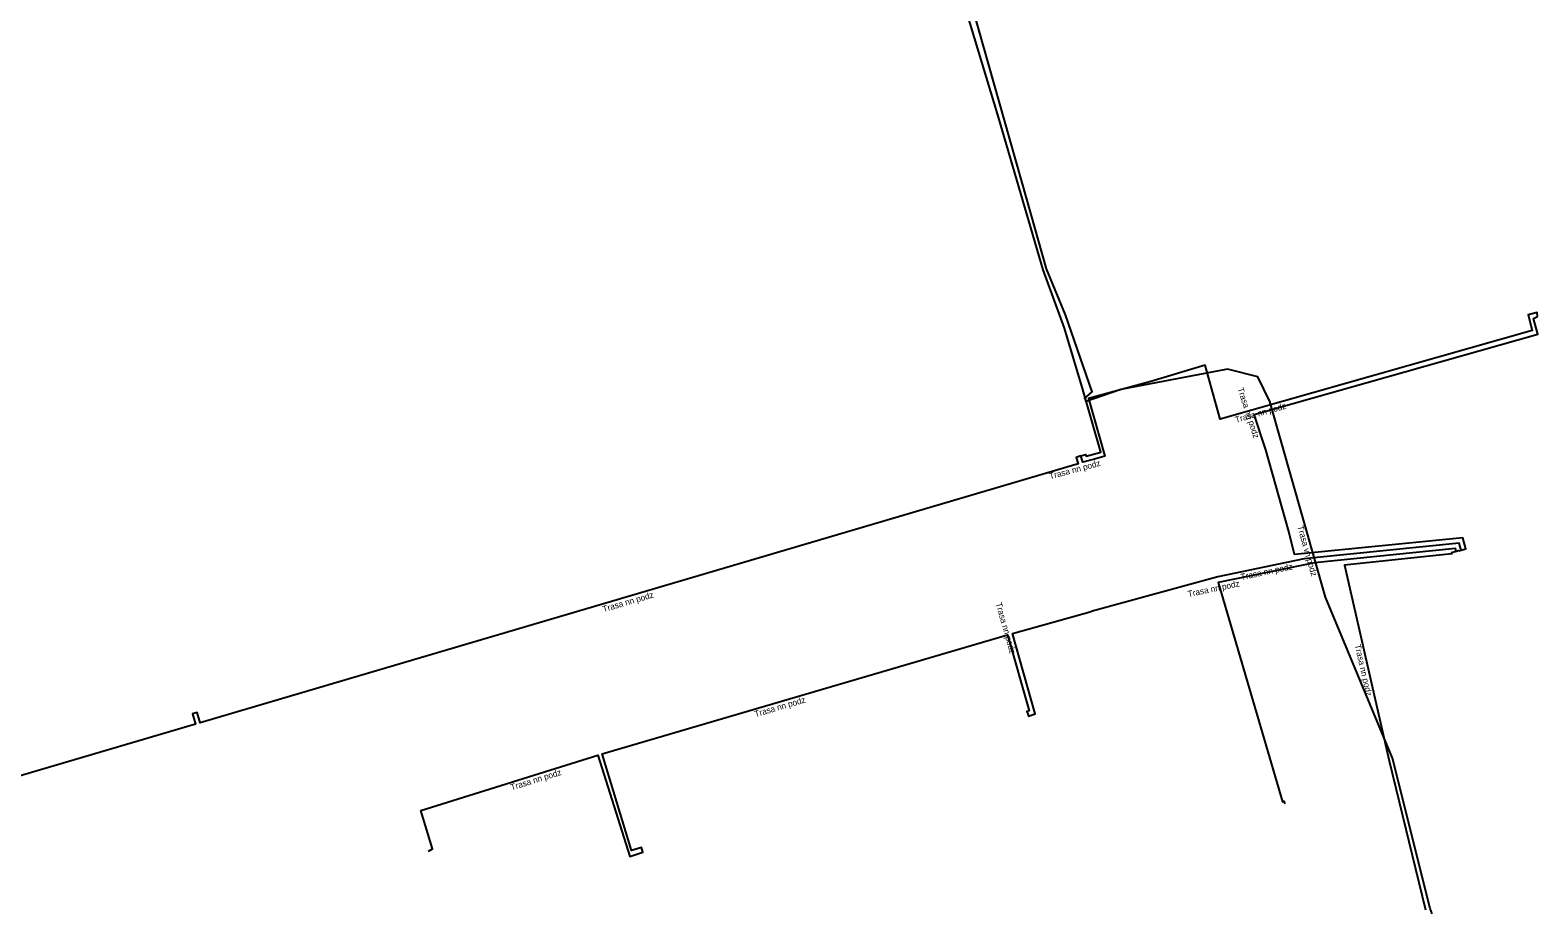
# Model space of a CAD drawing. Extents: x -690200 to -689130, y -975255 to -974631.
# Drawn here: x -689743.9 to -689621.6, y -975069.7 to -974998.1 of the extents above; entities that cross this region are included whole.
import ezdxf

# ---------------------------------------------------------------- set-up
doc = ezdxf.new("R2010")
doc.units = 0
for name, color, linetype in [('Popiskový text - Ostatní atributy Trasy', 7, 'Continuous'), ('Spojnice NN', 7, 'Continuous'), ('Spojnice VN', 7, 'Continuous')]:
    doc.layers.add(name, color=color, linetype=linetype)

msp = doc.modelspace()

# ---------------------------------------------------------------- linework, layer by layer
at = {"layer": 'Spojnice NN'}
for points in [[(-689658.68, -975032.57), (-689658.3, -975032.45), (-689658.25, -975032.6), (-689657.08, -975032.28), (-689658.52, -975027.18), (-689660.02, -975022.22), (-689661.74, -975017.49), (-689665.36, -975005.11), (-689668.28, -974995.43), (-689671.2, -974985.78), (-689677.14, -974966.45), (-689681.02, -974951.73), (-689687.6, -974930.95), (-689687.72, -974930.56), (-689688.33, -974927.89)], [(-689621.64, -975021.28), (-689621.68, -975020.94), (-689622.41, -975021.13), (-689622.08, -975022.42), (-689647.39, -975029.59), (-689648.6, -975025.23), (-689653, -975026.53), (-689658.06, -975027.92), (-689656.73, -975032.6), (-689657.59, -975032.84)], [(-689628.03, -975040.27), (-689627.46, -975040.11), (-689627.7, -975039.22), (-689641.36, -975040.58), (-689641.82, -975038.71), (-689643.68, -975032.09), (-689644.62, -975029.21), (-689621.62, -975022.7), (-689621.98, -975021.43), (-689621.64, -975021.28)], [(-689658.68, -975032.57), (-689659.06, -975032.7), (-689658.9, -975033.22), (-689730.12, -975054.21), (-689730.36, -975053.38), (-689730.55, -975053.44)], [(-689657.59, -975032.84), (-689658.52, -975033.09), (-689658.68, -975032.57)], [(-689628.03, -975040.27), (-689627.84, -975040.21), (-689628, -975039.65), (-689639.78, -975040.83), (-689640.58, -975040.92), (-689647.58, -975042.38), (-689657.84, -975045.19)], [(-689628.03, -975040.27), (-689628.23, -975040.32), (-689628.3, -975040.08), (-689639.74, -975041.23), (-689647.54, -975042.85), (-689647.27, -975043.76), (-689642.32, -975060.62), (-689642.21, -975060.58), (-689642.15, -975060.77)], [(-689628.03, -975040.27), (-689628.61, -975040.43), (-689628.59, -975040.51), (-689637.29, -975041.42), (-689633.69, -975057.29), (-689630.73, -975069.39)], [(-689662.99, -975053.48), (-689662.93, -975053.67), (-689662.4, -975053.49), (-689664.24, -975046.96), (-689657.84, -975045.19)], [(-689694.27, -975064.52), (-689694.33, -975064.33), (-689695.13, -975064.57), (-689697.52, -975056.74), (-689664.63, -975047.07), (-689662.89, -975053.23), (-689663.06, -975053.29), (-689662.99, -975053.48)], [(-689730.55, -975053.44), (-689730.74, -975053.49), (-689730.51, -975054.33), (-689766.77, -975065.01)], [(-689711.61, -975064.61), (-689711.27, -975064.43), (-689712.24, -975061.32), (-689697.88, -975056.84), (-689695.28, -975065.06), (-689694.21, -975064.71), (-689694.27, -975064.52)]]:
    msp.add_lwpolyline(points, dxfattribs=at)
at = {"layer": 'Spojnice VN'}
for points in [[(-689658.41, -975027.96), (-689657.77, -975027.37), (-689659.94, -975021.14), (-689661.47, -975017.42), (-689663.06, -975011.75), (-689664.86, -975005.47), (-689670, -974987.31), (-689670.83, -974984.38), (-689675.93, -974968.21), (-689678.07, -974960.76), (-689679.53, -974955.75), (-689680.26, -974949.49), (-689681.42, -974947.42), (-689682.76, -974943.93), (-689686.12, -974933.72)], [(-689630.19, -975069.7), (-689630.35, -975069.28), (-689633.4, -975057.07), (-689638.83, -975044.02), (-689643.36, -975028.15), (-689644.32, -975026.15), (-689646.78, -975025.55), (-689655.45, -975027.19), (-689658.34, -975028.2)]]:
    msp.add_lwpolyline(points, dxfattribs=at)

# ---------------------------------------------------------------- texts
at = {"layer": 'Popiskový text - Ostatní atributy Trasy'}
for s, rotation, p in [('Trasa nn podz', 288.0823, (-689645.99, -975027.12)), ('Trasa nn podz', 15.8126, (-689646.1, -975029.9)), ('Trasa nn podz', 15.0663, (-689661.18, -975034.48)), ('Trasa vn podz', 285.9149, (-689641.14, -975038.3)), ('Trasa nn podz', 11.7516, (-689645.66, -975042.64)), ('Trasa nn podz', 16.4218, (-689697.4, -975045.25)), ('Trasa nn podz', 11.768, (-689649.96, -975044.02)), ('Trasa nn podz', 285.7714, (-689665.6, -975044.54)), ('Trasa nn podz', 282.7824, (-689636.48, -975047.91)), ('Trasa nn podz', 16.3775, (-689685.08, -975053.76)), ('Trasa nn podz', 17.3154, (-689704.86, -975059.7))]:
    msp.add_text(s, height=0.5, rotation=rotation, dxfattribs=at).set_placement(p)

doc.saveas('drawing.dxf')
